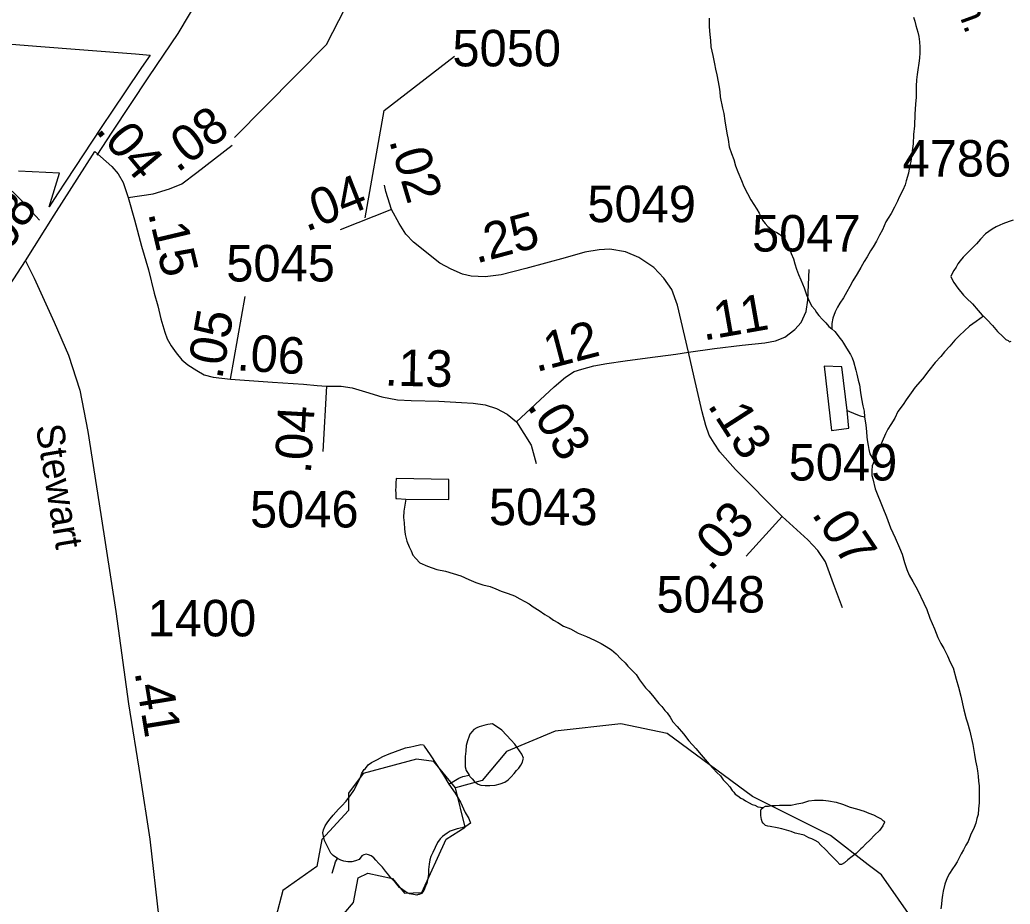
# Model space of a CAD drawing. Extents: x 2001466 to 2224147, y 644118 to 847247.
# Drawn here: x 2062288 to 2065678, y 678946 to 681973 of the extents above; entities that cross this region are included whole.
import ezdxf

# ---------------------------------------------------------------- set-up
doc = ezdxf.new("R2010")
doc.units = 0
for name, color, linetype in [('Exist Boundary Political City Limit New', 7, 'Continuous'), ('Exist Hydrographic Misc Water Feature', 7, 'Continuous'), ('Exist Road Non-System Type 51', 7, 'Continuous'), ('Exist Road Secondary Mileage Hundredths English Label', 7, 'Continuous'), ('Exist Road Secondary Type 51 Attributed', 7, 'Continuous'), ('Exist Road Secondary Type 51 Label', 7, 'Continuous'), ('Exist Road Secondary Type 51 Number Label', 7, 'Continuous'), ('Map Preparation Boundary City Limit Buffer Line', 7, 'Continuous')]:
    doc.layers.add(name, color=color, linetype=linetype)

msp = doc.modelspace()

# ---------------------------------------------------------------- linework, layer by layer
at = {"layer": 'Exist Boundary Political City Limit New'}
for points in [[(2062215.4, 681892.5), (2062345, 681882.4), (2062684.1, 681856.1), (2062734, 681852.2), (2062704.6, 681809.1), (2062648, 681726.7)], [(2062648, 681726.7), (2062605.8, 681663.9), (2062566.6, 681604.8), (2062445, 681420.8), (2062416.5, 681377.2), (2062388.6, 681333.2), (2062423.1, 681448.3), (2062283.5, 681454.3)]]:
    msp.add_lwpolyline(points, dxfattribs=at)
at = {"layer": 'Exist Hydrographic Misc Water Feature'}
for points in [[(2064647.5, 681978.7), (2064647.5, 681948.7), (2064649.5, 681922.4), (2064651.8, 681902.6), (2064653.6, 681880.8), (2064659.6, 681850.7), (2064665.5, 681822.6), (2064669.8, 681804.5), (2064673.7, 681784.9), (2064682.1, 681742.7), (2064684, 681726.6), (2064685.8, 681708.8), (2064693.8, 681670.7), (2064698.1, 681652.6), (2064701.8, 681626.9), (2064708, 681584.6), (2064712.1, 681562.9), (2064716, 681538.7), (2064724.4, 681514.8), (2064732.6, 681494.9), (2064738.3, 681472.9), (2064746.3, 681453), (2064758.4, 681422.8), (2064766.6, 681402.9), (2064778.7, 681378.8), (2064790.8, 681357.1), (2064810.5, 681324.9), (2064818.7, 681311.1), (2064824.4, 681299.2), (2064830.6, 681287), (2064838.8, 681275.2), (2064848.6, 681265.2), (2064858.7, 681257.1), (2064868.7, 681249.1), (2064878.8, 681245.2), (2064888.8, 681239.2), (2064894.6, 681233.1), (2064900.9, 681227.2), (2064906.7, 681223.1), (2064910.8, 681215.2), (2064916.9, 681203.3), (2064923.1, 681189.4), (2064928.8, 681173.1), (2064936.8, 681155.2), (2064940.7, 681137.2), (2064946.7, 681119.3), (2064953, 681101.3), (2064961, 681083.5), (2064972.9, 681055.3), (2064981.3, 681031.3), (2064985.2, 681021.4), (2064991.4, 681007.4), (2064999.2, 680993.3), (2065009.2, 680981.7), (2065015.1, 680971.4), (2065023.1, 680961.3), (2065035.4, 680947.7), (2065047.3, 680935.7), (2065057.2, 680923.6), (2065067.4, 680915.6)], [(2065347.1, 681981.8), (2065351.2, 681967.8), (2065355.1, 681953.8), (2065361.5, 681930.1), (2065365.6, 681916.1), (2065367.6, 681897.9), (2065369.3, 681879.8), (2065369.3, 681859.9), (2065367.6, 681842), (2065365.4, 681824), (2065361.7, 681801.9), (2065359.6, 681786), (2065357.4, 681768), (2065355.9, 681746), (2065355.9, 681707.9), (2065353.5, 681683.9), (2065351.8, 681650.1), (2065350.2, 681610.1), (2065347.7, 681580.1), (2065346.3, 681547.9), (2065342.2, 681524.1), (2065340.2, 681505.8), (2065337.9, 681487.9), (2065334, 681469.8), (2065330.5, 681448.1), (2065322.3, 681422.1), (2065318.2, 681408.1), (2065310.6, 681389.8), (2065298.5, 681365.7), (2065292.4, 681352), (2065282.5, 681332), (2065270.4, 681309.9), (2065260.6, 681294), (2065252.6, 681281.8), (2065246.9, 681267.7), (2065240.7, 681254), (2065230.4, 681236.1), (2065220.6, 681215.7), (2065208.9, 681195.9), (2065200.5, 681181.8), (2065188.8, 681161.7), (2065178.8, 681145.8), (2065167.1, 681125.7), (2065154.8, 681103.6), (2065139, 681079.6), (2065128.7, 681059.6), (2065119.1, 681041.6), (2065107.2, 681021.5), (2065095.3, 681003.5), (2065086.9, 680989.7), (2065079.1, 680973.5), (2065071.3, 680951.6), (2065067.4, 680933.5), (2065067.4, 680915.6)], [(2065688.5, 681286.7), (2065674.8, 681282.7), (2065652.7, 681274.7), (2065642.6, 681270.5), (2065630.5, 681264.7), (2065616.4, 681256.7), (2065594.2, 681240.6), (2065576.8, 681222.5), (2065562.6, 681206.4), (2065546.8, 681190.6), (2065538.6, 681182.5), (2065528.8, 681172.2), (2065516.7, 681160.3), (2065507.1, 681148.3), (2065498.9, 681138.2), (2065492.7, 681126.6), (2065484.7, 681114.4), (2065476.9, 681100.2), (2065475.1, 681094.3), (2065477.1, 681088.4), (2065484.9, 681074.2), (2065499.1, 681054.2), (2065518.8, 681030.5), (2065529, 681020.5), (2065549.1, 681000.4), (2065568.8, 680978.3), (2065582.7, 680962.4), (2065587.2, 680958.5)], [(2065587.2, 680958.5), (2065561.2, 680940.5), (2065539.1, 680924.5), (2065505.2, 680892.3), (2065489.2, 680876.4), (2065471.2, 680856.5), (2065453.3, 680836.4), (2065441.2, 680820.4), (2065421.4, 680800.3), (2065399.2, 680772.5), (2065377.7, 680744.1), (2065353.3, 680716.1), (2065339.5, 680696.3), (2065321.9, 680672.2), (2065311.4, 680655.9), (2065293.8, 680631.8), (2065283.8, 680609.8), (2065270, 680588), (2065259.6, 680572.2), (2065251.8, 680555.9), (2065239.9, 680530.1), (2065234.1, 680516), (2065228, 680503.9), (2065222, 680489.8), (2065216.1, 680474.1), (2065212, 680462.2)], [(2065587.2, 680958.5), (2065599.1, 680946.5), (2065617.2, 680926.8), (2065635, 680906.7), (2065652.9, 680888.5), (2065663.1, 680878.9), (2065671.3, 680874.8), (2065675.4, 680870.5), (2065681.4, 680872.9)], [(2065067.4, 680915.6), (2065077.3, 680905.6), (2065085.3, 680895.5), (2065095.3, 680883.8), (2065101.5, 680875.6), (2065107.6, 680865.8), (2065117.7, 680849.6), (2065131.4, 680827.7), (2065137.6, 680815.8), (2065141.5, 680803.8), (2065149.7, 680773.8), (2065153.6, 680759.8), (2065157.5, 680739.7), (2065161.8, 680723.7), (2065165.9, 680697.9), (2065169.3, 680675.9), (2065173.4, 680651.7), (2065177.8, 680633.6), (2065179.8, 680613.8)], [(2065119.7, 680635.5), (2065101.5, 680785.5), (2065041.4, 680787.7), (2065066, 680567.5), (2065125.9, 680575.8), (2065119.7, 680635.5)], [(2065119.7, 680635.5), (2065149.7, 680623.7), (2065164, 680617.9), (2065179.8, 680613.8)], [(2065179.8, 680613.8), (2065183.7, 680585.7), (2065186, 680563.8), (2065187.8, 680544.1), (2065189.8, 680528), (2065192.1, 680515.9), (2065194, 680501.8), (2065198.1, 680487.8), (2065204, 680475.9), (2065212, 680462.2)], [(2065212, 680462.2), (2065205.8, 680446.1), (2065204.2, 680430.1), (2065204.4, 680413.8), (2065207.9, 680401.9), (2065216.3, 680367.8), (2065242.3, 680302.2), (2065254.2, 680272), (2065268.8, 680234.1), (2065284.8, 680200.1), (2065298.7, 680166.3), (2065308.6, 680144.1), (2065316.8, 680116.1), (2065324.6, 680092.2), (2065332.8, 680072.3), (2065344.9, 680050.2), (2065360.9, 680022.2), (2065382.6, 679976.3), (2065393.1, 679954.5), (2065402.9, 679924.6), (2065419.1, 679888.5), (2065431, 679858.7), (2065440.8, 679838.5), (2065451.1, 679820.8), (2065463.2, 679796.6), (2065473, 679774.4), (2065483.5, 679754.6), (2065493.1, 679716.6), (2065501.3, 679688.6), (2065509.5, 679658.6), (2065519.4, 679610.8), (2065527.6, 679580.8), (2065531.7, 679566.8), (2065539.7, 679538.8), (2065549.9, 679492.7), (2065555.7, 679458.9), (2065559.6, 679436.8), (2065563.9, 679416.7), (2065565.9, 679402.6), (2065568, 679384.9), (2065570, 679366.7), (2065571.7, 679351), (2065572.1, 679332.7), (2065572.1, 679314.9), (2065572.3, 679293), (2065570.2, 679273), (2065568.2, 679253), (2065564.5, 679239), (2065560.2, 679223), (2065554.4, 679208.9), (2065541.9, 679182.7), (2065534.5, 679160.8), (2065526.5, 679148.6), (2065518.3, 679132.8), (2065510.6, 679119), (2065496.4, 679090.7), (2065488.4, 679078.5), (2065480.6, 679066.7), (2065470.6, 679050.8), (2065462.8, 679036.6), (2065454.4, 679014.7)], [(2063608.9, 680332.8), (2063756.5, 680331.5), (2063756.3, 680399.3), (2063576.3, 680403.1), (2063574.4, 680387.1), (2063574.7, 680374.9), (2063574.2, 680362.8), (2063574.9, 680353), (2063574.7, 680334.8), (2063578.6, 680335), (2063608.9, 680332.8)], [(2063608.9, 680332.8), (2063602.7, 680291.1), (2063600.7, 680269.2), (2063603, 680251), (2063604.6, 680230.9), (2063606.8, 680211), (2063613, 680189), (2063620.6, 680169.2), (2063626.9, 680155.3), (2063632.9, 680140.9), (2063642.9, 680129.3), (2063657.1, 680115), (2063682.9, 680103.4), (2063714.7, 680091.3), (2063745.3, 680085.4), (2063771.1, 680077.4), (2063796.9, 680069.4), (2063825.2, 680057.5), (2063849, 680047.4), (2063873.2, 680039.7), (2063897.4, 680033.6), (2063917.3, 680025.7), (2063935.1, 680017.7), (2063959.1, 680009.6), (2063981.3, 680001.8), (2063999.1, 679991.8), (2064017, 679981.8), (2064031.1, 679973.9), (2064045, 679963.7), (2064065.1, 679951.7), (2064085.4, 679937.7), (2064101.2, 679928.1), (2064115.2, 679917.8), (2064129.1, 679910), (2064149.2, 679898), (2064173.2, 679888.3), (2064199.2, 679874.2), (2064227.5, 679862.2), (2064255.2, 679850.3), (2064277.6, 679838.4), (2064295.4, 679828.4), (2064313.3, 679816.4), (2064329.2, 679802.6), (2064345.2, 679786.4), (2064359.6, 679772.5), (2064369.4, 679760.4), (2064381.5, 679748.4), (2064397.5, 679732.6), (2064409.4, 679714.6), (2064419.9, 679700.4), (2064429.5, 679686.8), (2064441.4, 679674.9), (2064453.7, 679660.9), (2064475.7, 679632.8), (2064485.5, 679622.8), (2064496, 679608.6), (2064503.5, 679600.9), (2064514, 679586.8), (2064523.6, 679570.7)], [(2065192, 679081.3), (2065062.5, 679181), (2064795.5, 679314.3), (2064503.5, 679530.3), (2064345.7, 679563), (2064120.5, 679538.1), (2063953.6, 679469.2), (2063870.5, 679369.3), (2063779.5, 679344.9)], [(2063970, 679507.8), (2063938.2, 679541.9), (2063906.2, 679563.8), (2063890, 679561.7), (2063876.3, 679557.8), (2063867.9, 679555.8), (2063859.9, 679553.7), (2063851.9, 679549.7), (2063842, 679543.5), (2063835.9, 679537.5), (2063827.9, 679527.8), (2063826, 679521.6), (2063819.9, 679505.4), (2063816, 679489.4), (2063814.4, 679469.4), (2063812.1, 679451.5), (2063812.5, 679437.6), (2063812.5, 679427.5), (2063812.1, 679415.8), (2063816, 679403.4), (2063822.2, 679393.6), (2063826.3, 679387.7)], [(2064523.6, 679570.7), (2064538, 679554.8), (2064559.9, 679529.1), (2064577.8, 679505), (2064601.8, 679479), (2064619.8, 679457.2), (2064633.7, 679441.3), (2064648.1, 679425), (2064661.8, 679411.1), (2064673.9, 679397.1), (2064686, 679385.1), (2064696.1, 679371.4), (2064708, 679359), (2064718, 679347.4), (2064726.2, 679335.2), (2064732, 679329.5), (2064736.1, 679323.1), (2064746.1, 679317.2), (2064756.4, 679309.2), (2064764.2, 679305.5), (2064772.2, 679299.5), (2064784.3, 679293.6), (2064794.3, 679287.6), (2064804.1, 679285.3), (2064814.2, 679279.3), (2064832.2, 679277.4)], [(2063374.9, 679102.8), (2063360.8, 679112.7), (2063352.8, 679120.8), (2063345, 679134.6), (2063337, 679150.7), (2063330.8, 679164.6), (2063326.7, 679178.6), (2063324.5, 679190.7), (2063326.7, 679201), (2063332.7, 679214.7), (2063342.3, 679228.6), (2063350.3, 679238.8), (2063360.4, 679250.6), (2063378.6, 679271), (2063390.5, 679283), (2063404.7, 679298.7), (2063420.7, 679321), (2063430.7, 679334.9), (2063442.4, 679357), (2063452.4, 679377), (2063458.4, 679394.8), (2063466.4, 679406.9), (2063470.5, 679410.8), (2063480.1, 679423.1), (2063492, 679431), (2063512.5, 679440.9), (2063530.4, 679451.2), (2063552.3, 679461.3), (2063574.2, 679469.3), (2063608.1, 679481.2), (2063626.1, 679485.3), (2063636.2, 679487), (2063660.2, 679493.2), (2063670, 679491.2), (2063671.8, 679487.3), (2063691.9, 679457.5), (2063738.3, 679387.6), (2063756.1, 679357.3)], [(2063826.3, 679387.7), (2063828.5, 679383.7), (2063836.1, 679375.6), (2063842.5, 679367.8), (2063850.2, 679361.7), (2063856.4, 679357.5), (2063866.4, 679353.6), (2063880.6, 679351.9), (2063896.4, 679351.9), (2063914.4, 679353.6), (2063932.1, 679357.9), (2063948.5, 679363.9), (2063959.9, 679371.8), (2063970.2, 679382.1), (2063980.2, 679393.9), (2063988.2, 679404.1), (2063996.4, 679411.8), (2064002.4, 679421.8), (2064008.3, 679431.9), (2064010.4, 679442.1), (2064011.8, 679445.9), (2064006.1, 679459.8), (2063982.1, 679493.9), (2063970, 679507.8)], [(2063779.5, 679344.9), (2063704.7, 679435), (2063645.6, 679442.7), (2063462.7, 679393.9), (2063412.7, 679326.1), (2063412.7, 679267), (2063321.6, 679167.2), (2063304.6, 679075.6), (2063188.5, 678992.8), (2063163.5, 678901.4), (2063180.5, 678786.2), (2063330.6, 678835.6), (2063429.7, 678951.7), (2063446.5, 679036.7), (2063479.5, 679052.4), (2063563.6, 679034.3), (2063604.6, 678984.2), (2063663.6, 678986.3), (2063746.7, 679168.4), (2063812.5, 679209.7), (2063779.5, 679344.9)], [(2063756.1, 679357.3), (2063790.2, 679377.7), (2063804.3, 679383.7), (2063826.3, 679387.7)], [(2063756.1, 679357.3), (2063778.5, 679325.6), (2063796.3, 679295.7), (2063812.5, 679259.6), (2063824.4, 679239.5), (2063830.8, 679223.5), (2063814.8, 679211.8), (2063800.4, 679207.4), (2063784.4, 679203.8), (2063770.7, 679199.8), (2063760.6, 679195.7), (2063750.6, 679189.5), (2063734.6, 679177.7), (2063727, 679169.5), (2063717, 679157.7), (2063701, 679123.5), (2063694.8, 679109.5), (2063691.1, 679097.5), (2063688.9, 679083.6), (2063686.6, 679065.3), (2063687, 679049.5), (2063685, 679035.5), (2063680.7, 679017.5), (2063677, 679007.5), (2063671.2, 678993.4), (2063663.2, 678983.3), (2063654.8, 678979.3), (2063650.9, 678979.4), (2063646.8, 678977.2), (2063635.3, 678979.4), (2063621.2, 678981.1), (2063607.3, 678989.3), (2063599.3, 678995.4), (2063587, 679003.3), (2063578.8, 679015.1), (2063573, 679021.3), (2063557, 679037.1), (2063551.1, 679045.3), (2063539, 679059.3), (2063528.9, 679073), (2063516.8, 679084.9), (2063506.6, 679097.1), (2063499, 679105.1), (2063490.6, 679111.2), (2063481.2, 679115.1), (2063472.9, 679117.2), (2063465, 679115.1), (2063458.8, 679111.2), (2063448.8, 679098.9), (2063436.9, 679095), (2063424.8, 679090.8), (2063410.8, 679090.9), (2063397.1, 679093), (2063386.6, 679097), (2063374.9, 679102.8)], [(2064832.2, 679277.4), (2064840, 679281.5), (2064850.3, 679281.5), (2064862, 679283.4), (2064874.5, 679283.5), (2064888.4, 679285.5), (2064906.3, 679285.6), (2064928.2, 679285.5), (2064948.1, 679289.8), (2064968.4, 679293.6), (2064988.5, 679299.9), (2065008.4, 679301.8), (2065021.9, 679301.7), (2065038.1, 679301.7), (2065056.2, 679299.8), (2065082.2, 679295.9), (2065104.3, 679288), (2065130.2, 679278), (2065152.1, 679272.2), (2065178.2, 679264.3), (2065194.2, 679258.2), (2065210.1, 679252.1), (2065224.5, 679244.3), (2065236.2, 679238.4), (2065242.1, 679232.3), (2065246.4, 679230.4), (2065248.3, 679226.5), (2065242.5, 679214.4), (2065230.4, 679198.3), (2065214, 679182.2), (2065198.3, 679166.3), (2065182.3, 679152.1), (2065172.2, 679140.2)], [(2065172.2, 679140.2), (2065166.5, 679136.2), (2065150.7, 679120), (2065136.7, 679109.9), (2065122.4, 679097.9), (2065110.5, 679088), (2065100.7, 679082.2), (2065094.5, 679081.9), (2065084.7, 679093.9), (2065064.2, 679114), (2065044.7, 679134), (2065030.3, 679148), (2065020.5, 679158), (2065010.4, 679164), (2064998.7, 679169.8), (2064988.3, 679173.8), (2064980.5, 679177.8), (2064972.3, 679181.9), (2064958.3, 679185.6), (2064942.6, 679189.7), (2064928.2, 679195.5), (2064912.2, 679199.5), (2064896.4, 679203.6), (2064880.4, 679207.6), (2064856.4, 679211.7), (2064848.2, 679213.7), (2064840.2, 679215.7), (2064836.5, 679219.5), (2064832, 679223.4), (2064828.5, 679227.6), (2064826.5, 679235.6), (2064824, 679249.4), (2064824.2, 679255.4), (2064824.2, 679265.6), (2064826.1, 679271.4), (2064832.2, 679277.4)], [(2063356.9, 679052.8), (2063364.9, 679078.8), (2063368.6, 679090.8), (2063374.9, 679102.8)], [(2065413.6, 678557.1), (2065354.5, 678879.8), (2065237.6, 679046.2), (2065192, 679081.3)], [(2065454.4, 679014.7), (2065448.8, 678990.9), (2065446.8, 678976.6), (2065444.5, 678960.7), (2065442.7, 678946.7), (2065440.4, 678930.8)]]:
    msp.add_lwpolyline(points, dxfattribs=at)
at = {"layer": 'Exist Road Non-System Type 51'}
msp.add_lwpolyline([(2060765.6, 681963.3), (2061241, 681933.7), (2061276.8, 681924.9), (2061302.7, 681918.4), (2061322.5, 681908), (2061363.7, 681869.2), (2061375.3, 681850.9), (2061384.7, 681818.8), (2061383.5, 681762.8), (2061381.3, 681556.8), (2061384.7, 681524.8), (2061392.3, 681508.6), (2061405.8, 681484.3), (2061421.4, 681464), (2061449.3, 681455.4), (2061483.1, 681448.8), (2061541.1, 681445.6), (2062133.4, 681446.9), (2062184.6, 681446.9), (2062230.1, 681415.7), (2062292.6, 681355.9), (2062355.1, 681287.7)], dxfattribs=at)
at = {"layer": 'Exist Road Secondary Type 51 Attributed'}
for points in [[(2062552.8, 681509.3), (2062603.2, 681588.2), (2062728.7, 681777.3), (2062829.7, 681925.7), (2062903.8, 682052), (2062974.8, 682205.2), (2063019, 682313), (2063075, 682472.4), (2063127.1, 682698.2), (2063169.7, 682896.8), (2063208.4, 682980.5), (2063244.6, 683045.2), (2063312.5, 683113.1), (2063440.3, 683234.7), (2063629.7, 683395.4), (2063787.4, 683539.1)], [(2062658.4, 681364.3), (2062744, 681377.1), (2062799.6, 681394.2), (2062842.4, 681411.4), (2062893.8, 681449.9), (2063014, 681543.6)], [(2062307, 681148), (2062405.6, 681304.7), (2062544.5, 681521.8)], [(2062544.5, 681521.8), (2062602.8, 681471.3), (2062624.2, 681445.6), (2062641.3, 681415.6), (2062658.4, 681364.3)], [(2063560.2, 681323.2), (2063547.4, 681364), (2063540.9, 681385.5), (2063536.6, 681407)], [(2062658.4, 681364.3), (2062680.7, 681288.8), (2062704.3, 681198.5), (2062728, 681116.9), (2062747.3, 681037.4), (2062760.2, 680994.4), (2062770.9, 680949.3), (2062783.8, 680904.2), (2062792.4, 680880.5), (2062805.3, 680856.9), (2062822.4, 680833.3), (2062841.8, 680809.6), (2062863.2, 680792.5), (2062893.3, 680773.1), (2062919.1, 680758.1), (2062949.1, 680749.5), (2063009.3, 680743)], [(2063560.2, 681323.2), (2063384.5, 681253.6)], [(2064576.5, 680835.4), (2064539.4, 680996.6), (2064520.1, 681050.3), (2064492.2, 681089), (2064457.8, 681125.5), (2064406.3, 681159.9), (2064361.2, 681179.2), (2064307.5, 681187.8), (2064271, 681185.6), (2064221.6, 681177.1), (2064155, 681157.7), (2064019.8, 681121.2), (2063936, 681099.7), (2063880.2, 681093.3), (2063832.9, 681095.4), (2063802.9, 681101.9), (2063764.2, 681119), (2063725.6, 681140.5), (2063635.4, 681211.4), (2063609.6, 681239.4), (2063586, 681275.9), (2063560.2, 681323.2)], [(2060508, 679534.3), (2060552.2, 679608.9), (2060600.6, 679656.5), (2060652.2, 679690.1), (2060798.9, 679760.6), (2061116.9, 679901.7), (2061264.5, 679972.2), (2061371, 680032.9), (2061466.1, 680108.3), (2061569.4, 680213.3), (2061756.2, 680423.2), (2061943.1, 680639.7), (2062112, 680856.2), (2062225, 681020.9), (2062307, 681148)], [(2062307, 681148), (2062336.2, 681088.2), (2062404.8, 680938.6), (2062453.8, 680824.9), (2062493.2, 680704.9), (2062520.8, 680564), (2062565, 680280.1), (2062616.3, 679947.8), (2062659.7, 679632.3), (2062699.9, 679382.9), (2062733.1, 679169.3), (2062763, 678896.9)], [(2064576.5, 680835.4), (2064665.9, 680848.3), (2064760.3, 680859.1), (2064837.7, 680867.7), (2064874.2, 680874.1), (2064906.4, 680887), (2064940.7, 680912.8), (2064962.2, 680936.4), (2064979.4, 680975.1), (2064985.8, 681013.8), (2064990.4, 681118.2)], [(2063009.3, 680743), (2063059.1, 681025.5)], [(2063988.4, 680596.9), (2064117, 680717.3), (2064155.7, 680749.5), (2064185.7, 680768.8), (2064211.5, 680777.4), (2064252.3, 680788.2), (2064297.4, 680796.8), (2064359.7, 680805.3), (2064437, 680816.1), (2064533.6, 680829), (2064576.5, 680835.4)], [(2064897.8, 680272.5), (2064737.6, 680433.6), (2064683.9, 680493.8), (2064664.6, 680523.9), (2064647.4, 680551.8), (2064636.7, 680584), (2064623.8, 680631.3), (2064595.9, 680749.5), (2064576.5, 680835.4)], [(2063009.3, 680743), (2063153.1, 680732.3), (2063258.3, 680725.8), (2063305.6, 680721.5), (2063337.8, 680719.4)], [(2063337.8, 680719.4), (2063325.1, 680495.6)], [(2063337.8, 680719.4), (2063387.2, 680719.4), (2063425.8, 680713), (2063470.9, 680700.1), (2063526.7, 680682.9), (2063580.4, 680672.1), (2063627.7, 680670), (2063722.1, 680667.8), (2063799.4, 680663.5), (2063840.2, 680661.4), (2063881, 680654.9), (2063919.7, 680642.1), (2063956.2, 680622.7), (2063988.4, 680596.9)], [(2063988.4, 680596.9), (2064037.8, 680517.4), (2064055.8, 680454.2)], [(2064897.8, 680272.5), (2064774.7, 680137.6)], [(2065103.9, 679960.9), (2065073.8, 680042.6), (2065045.9, 680117.8), (2065020.2, 680156.5), (2064985.8, 680193), (2064897.8, 680272.5)]]:
    msp.add_lwpolyline(points, dxfattribs=at)
at = {"layer": 'Exist Road Secondary Type 51 Number Label'}
for points in [[(2063022.5, 681569.7), (2063337, 681888.2), (2063401.4, 682013.1)], [(2063470, 681295.6), (2063534.5, 681662.4), (2063776.3, 681847.9)]]:
    msp.add_lwpolyline(points, dxfattribs=at)
at = {"layer": 'Map Preparation Boundary City Limit Buffer Line'}
for points in [[(2062215.4, 681892.5), (2062345, 681882.4), (2062684.1, 681856.1), (2062734, 681852.2), (2062704.6, 681809.1), (2062648, 681726.7)], [(2062648, 681726.7), (2062605.8, 681663.9), (2062566.6, 681604.8), (2062445, 681420.8), (2062416.5, 681377.2), (2062388.6, 681333.2), (2062423.1, 681448.3), (2062283.5, 681454.3)]]:
    msp.add_lwpolyline(points, dxfattribs=at)

# ---------------------------------------------------------------- texts
at = {"layer": 'Exist Road Secondary Mileage Hundredths English Label'}
for s, rotation, p in [('.08', 36.8873, (2062827.1, 681447.4)), ('.04', 309.7869, (2062543.5, 681593.5)), ('.02', 286.6896, (2063550.9, 681559.8)), ('.04', 21.5785, (2063268.1, 681246.7)), ('.08', 57.3989, (2062225.9, 681136.5)), ('.15', 283.3835, (2062726.1, 681311.2)), ('.25', 15.1101, (2063850.2, 681138.2)), ('.11', 10.0144, (2064628.3, 680874.7)), ('.05', 79.9937, (2062979.6, 680739.6)), ('.12', 14.7525, (2064055.2, 680766.4)), ('.06', 356.4942, (2063028.2, 680773.4)), ('.13', 358.697, (2063535.5, 680721.3)), ('.04', 86.7515, (2063283.8, 680417)), ('.03', 301.8498, (2064021.7, 680651.3)), ('.13', 302.7185, (2064639.7, 680653.7)), ('.03', 47.6206, (2064652.7, 680082)), ('.07', 303.673, (2064996.1, 680281.4)), ('.41', 279.3163, (2062680.1, 679740.8))]:
    msp.add_text(s, height=125, rotation=rotation, dxfattribs=at).set_placement(p)
at = {"layer": 'Exist Road Secondary Type 51 Label'}
for s, rotation, p in [('Vintage Ridge Ln.', 289.9684, (2065183, 682869.8)), ('Stewart', 279.4214, (2062341.6, 680581.8))]:
    msp.add_text(s, height=95, rotation=rotation, dxfattribs=at).set_placement(p)
at = {"layer": 'Exist Road Secondary Type 51 Number Label'}
for s, p in [('5050', (2063768.6, 681813.5)), ('4786', (2065309.7, 681436.1)), ('5049', (2064230.5, 681280.2)), ('5047', (2064794.4, 681179.8)), ('5045', (2062994.4, 681077.3)), ('5049', (2064919.6, 680396.2)), ('5043', (2063893.6, 680243.5)), ('5046', (2063075.6, 680235.4)), ('5048', (2064467.1, 679944.2)), ('1400', (2062725.1, 679862.8))]:
    msp.add_text(s, height=125, dxfattribs=at).set_placement(p)

doc.saveas('drawing.dxf')
